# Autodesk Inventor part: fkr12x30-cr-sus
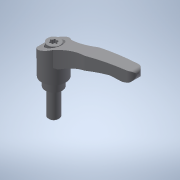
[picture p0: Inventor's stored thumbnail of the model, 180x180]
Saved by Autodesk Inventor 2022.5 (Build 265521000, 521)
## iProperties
Created: 2017-09
Part Number: fkr12x30-cr-sus
Material: 一般
Document SubType Name: Modeling
Designer: imaocorp
Density: 1 g/cm^3
Appearance: 既定
Author: imaocorp
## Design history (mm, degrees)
node "fkr12x30-cr-sus.x_t1"
node "fkr12x30-cr-sus"
node "Base1"
